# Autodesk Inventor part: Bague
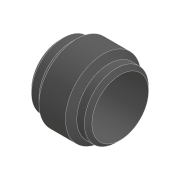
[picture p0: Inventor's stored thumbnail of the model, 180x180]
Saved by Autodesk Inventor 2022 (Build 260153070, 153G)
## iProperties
Created: 2018-06
Part Number: Bague
Material: Laiton, jaune doux
Document SubType Name: Modeling
Designer: Fabian Perrée
Density: 8.47 g/cm^3
Appearance: Générique
Mass: 1.57799 g
Surface Area: 4.49046 cm^2
Volume: 0.186303 cm^3
Author: Fabian Perrée
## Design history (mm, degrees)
sketch "Esquisse1"
  geometry: L1 (0, 0)-(8, 0); L2 (0, 3.75)-(8, 3.75); L3 (4, 0)-(4, 10.788); L4 (8, 3.75)-(8, 3.75); L5 (7.5, 4.25)-(6.5, 4.25); L6 (6.5, 4.25)-(6.5, 4.25); L7 (5.75, 5)-(2.25, 5); L8 (1.5, 4.25)-(1.5, 4.25); L9 (1.5, 4.25)-(0.5, 4.25); L10 (0, 3.75)-(0, 3.75); L11 (1.5, 4.25)-(2.25, 5); L12 (5.75, 5)-(6.5, 4.25); L13 (0.5, 4.25)-(0, 3.75); L14 (7.5, 4.25)-(8, 3.75); 4 further points
  constraints: 28 end point, 10 point on line, 5 perpendicular, 2 horizontal, 2 vertical, 2 vertical alignment, 1 midpoint, 1 other
  dimensions: "d0" = 8 distance of L2.start L2.end; "d2" = 7.5 diameter of L2 L1; "d3" = 8.5 diameter of L5 L1; "d4" = 10 diameter of L7 L1; "d6" = 0.75 distance of L8.start point (1.5, 5); "d7" = 0.75 distance of L7.end point (1.5, 5) (= d6); "d8" = 0.75 distance of L7.start point (6.5, 5) (= d6); "d9" = 0.75 distance of L6.end point (6.5, 5) (= d8); "d10" = 0.5 distance of L9.end point (0, 4.25); "d11" = 0.5 distance of L10.start point (0, 4.25) (= d10); "d12" = 0.5 distance of L5.start point (8, 4.25) (= d10); "d13" = 0.5 distance of L4.end point (8, 4.25) (= d12); "d14" = 3.5 distance of L7.start L7.end
revolve "Révolution1" sketch "Esquisse1" stored, may be unused: angle "d5" = 90 deg
node "Solide1"
